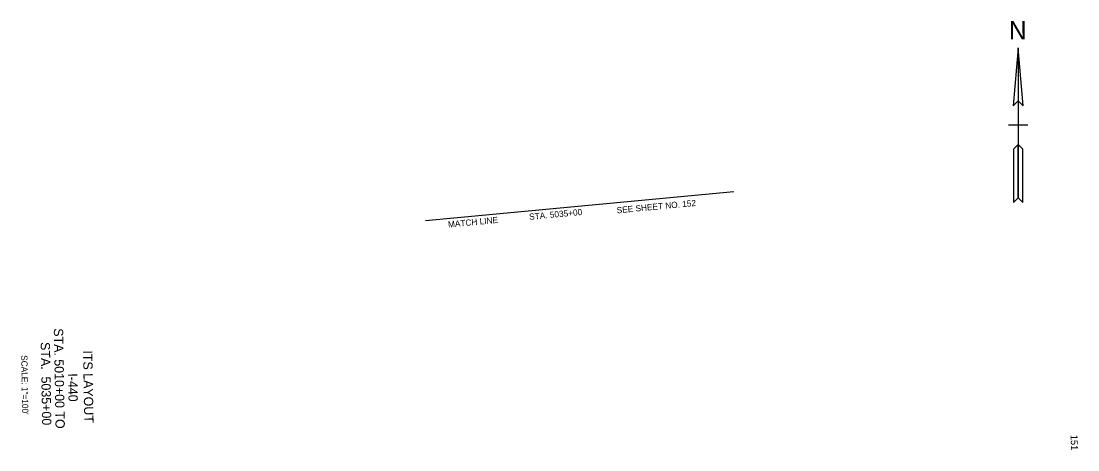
# Model space of a CAD drawing. Extents: x -200 to 1726806, y -325 to 663838.
# Drawn here: x 1724758 to 1726806, y 660835 to 661666 of the extents above; entities that cross this region are included whole.
import ezdxf

# ---------------------------------------------------------------- set-up
doc = ezdxf.new("R2010")
doc.units = 0
for name, color, linetype in [('DESIGN - CENTERLINE - Proposed Text', 7, 'Continuous'), ('DESIGN - SCRATCH - User 1', 7, 'Continuous'), ('DESIGN - SHEET - Corner Text', 7, 'Continuous'), ('ITS - CONST TEXT', 7, 'Continuous'), ('ITS - EXISITING WEATHER STATION', 7, 'Continuous'), ('ITS - EXISTING COMM CABLE', 7, 'Continuous'), ('ITS - EXISTING HAR', 7, 'Continuous')]:
    doc.layers.add(name, color=color, linetype=linetype)

msp = doc.modelspace()

# ---------------------------------------------------------------- linework, layer by layer
at = {"layer": 'DESIGN - CENTERLINE - Proposed Text'}
for p, q in [((1726690.1, 661464.6), (1726671.2, 661464.6)), ((1726709, 661464.6), (1726690.1, 661464.6))]:
    msp.add_line(p, q, dxfattribs=at)
msp.add_lwpolyline([(1726690.1, 661614.6), (1726680.3, 661502), (1726690.1, 661511.8), (1726699.9, 661502), (1726690.1, 661614.6), (1726690.1, 661323.7), (1726699.2, 661314.6), (1726699.2, 661418.1), (1726690.1, 661427.2), (1726681, 661418.1), (1726681, 661314.6), (1726690.1, 661323.7)], dxfattribs=at)
for points in [[(1726690.1, 661511.8), (1726699.9, 661502), (1726690.1, 661614.6)], [(1726681, 661314.6), (1726690.1, 661323.7), (1726690.1, 661427.2), (1726681, 661418.1)]]:
    msp.add_lwpolyline(points, close=True, dxfattribs=at)
at = {"layer": 'DESIGN - SCRATCH - User 1'}
msp.add_line((1724845.6, 660941.7), (1724845.6, 660941.7), dxfattribs=at)
at = {"layer": 'ITS - EXISITING WEATHER STATION'}
msp.add_line((1724845.6, 660941.8), (1724845.6, 660941.8), dxfattribs=at)
msp.add_line((1724845.6, 660941.8), (1724845.6, 660941.8), dxfattribs=at)
at = {"layer": 'ITS - EXISTING COMM CABLE'}
msp.add_line((1725541.7, 661279.9), (1726139.1, 661336.1), dxfattribs=at)

# ---------------------------------------------------------------- texts
at = {"layer": 'DESIGN - CENTERLINE - Proposed Text'}
msp.add_text('N', height=35.4, dxfattribs=at).set_placement((1726672, 661630.7))
at = {"layer": 'DESIGN - SHEET - Corner Text'}
msp.add_text('151', height=13.5, rotation=270.9938, dxfattribs=at).set_placement((1726791.7, 660864.3))
at = {"layer": 'ITS - CONST TEXT'}
msp.add_text('SCALE: 1"=100\'', height=12, rotation=270.9939, dxfattribs=at).set_placement((1724758.2, 661018.6))
at = {"layer": 'ITS - EXISTING COMM CABLE'}
for s, p in [('STA. 5035+00', (1725743.1, 661280.8)), ('SEE SHEET NO. 152 ', (1725912.6, 661293.5)), ('MATCH LINE', (1725585.8, 661266))]:
    msp.add_text(s, height=12, rotation=5.3727, dxfattribs=at).set_placement(p)
at = {"layer": 'ITS - EXISTING HAR'}
for s, p in [('STA. 5010+00 TO', (1724821.4, 661070.7)), ('STA.  5035+00', (1724795.9, 661043.9)), ('ITS LAYOUT', (1724878, 661027.7)), ('I-440', (1724848.9, 660983.3))]:
    msp.add_text(s, height=18, rotation=270.9939, dxfattribs=at).set_placement(p)

doc.saveas('drawing.dxf')
